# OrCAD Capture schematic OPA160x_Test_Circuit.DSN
size A; title: OPA160x, SoundPlus™ High-Performance, Bipolar-Input; rev: 1.4; note: Datasheet: SBOS474B   EVM: N/A
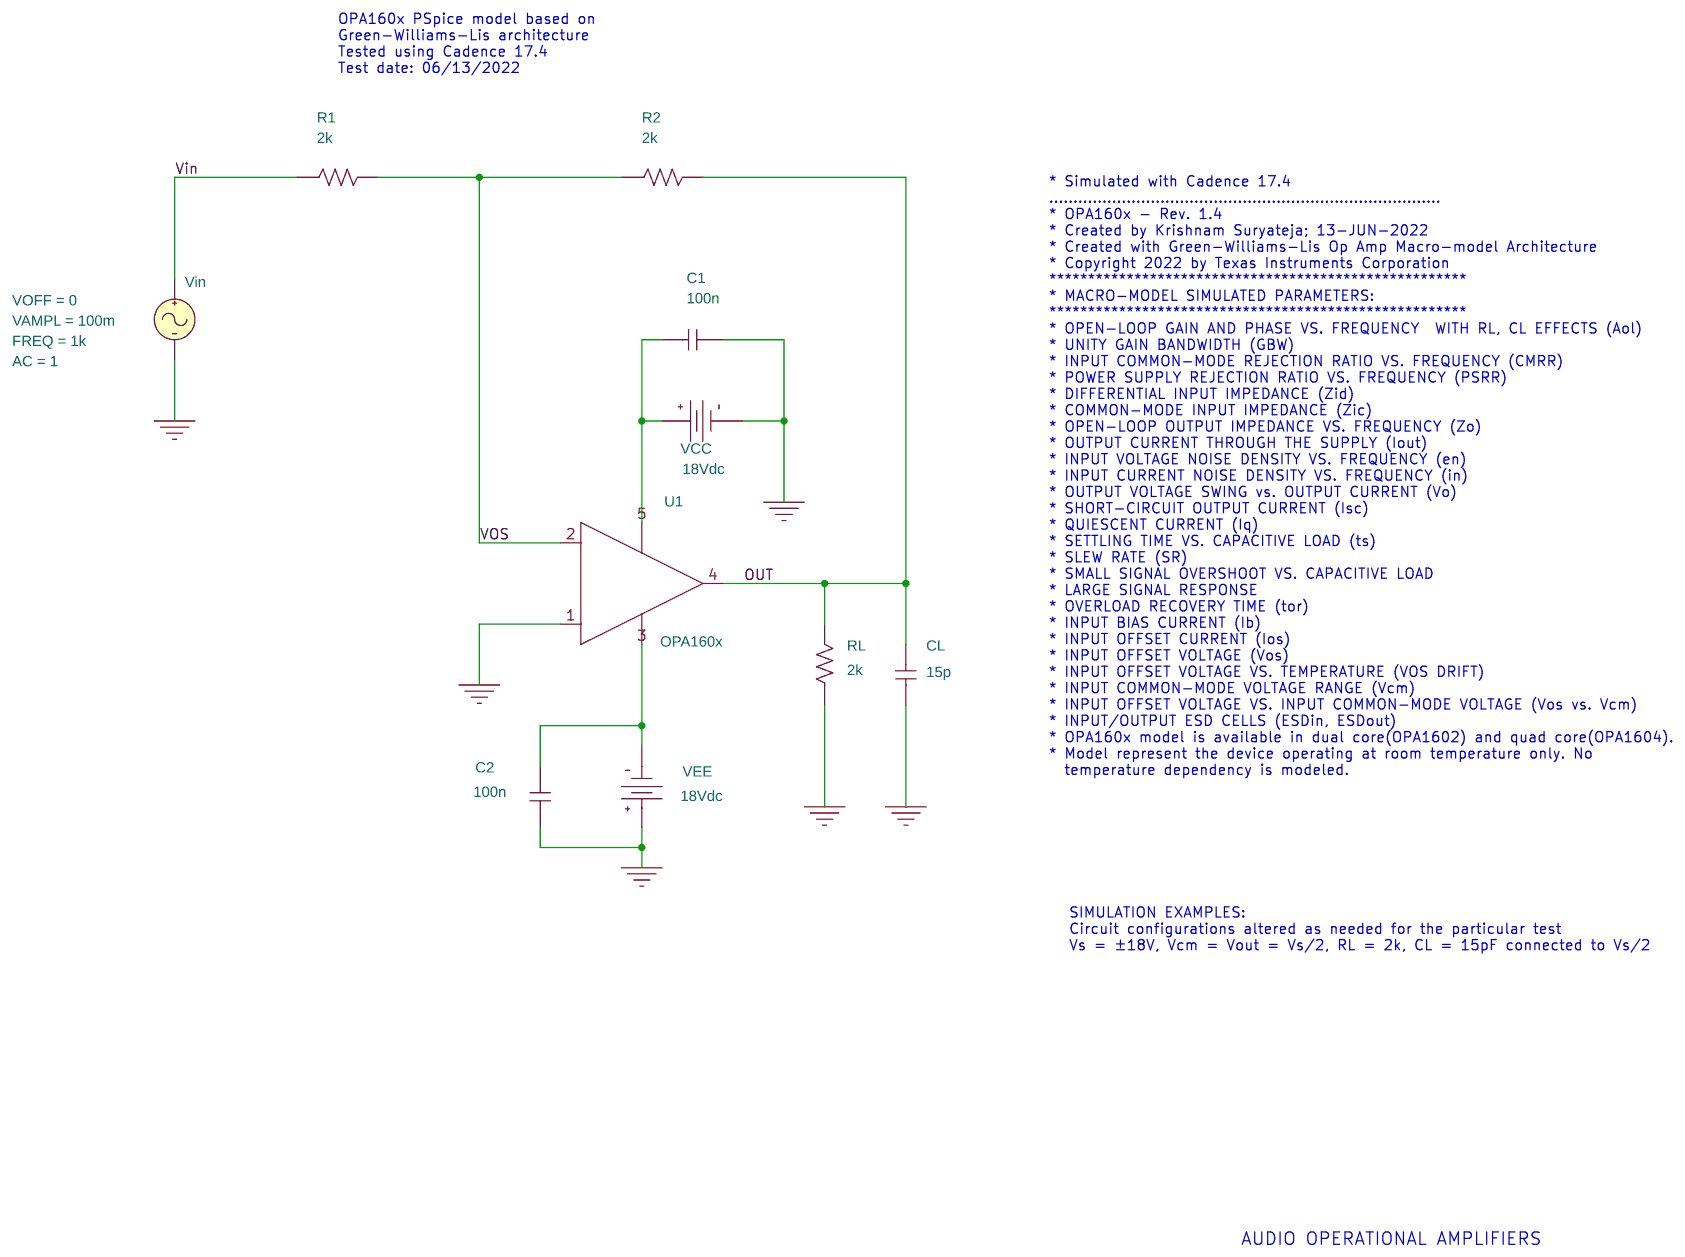
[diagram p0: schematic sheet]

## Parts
C1  100n  [cap196]
C2  100n  [cap196]
CL  15p  [cap196]
R1  2k  [AXRC05]
R2  2k  [AXRC05]
RL  2k  [AXRC05]
U1  OPA160x
VCC  VDC
VEE  VDC
Vin  VSIN

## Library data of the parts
C1 C2 CL = C
R1 R2 RL = R
U1 = OPA160x
VCC VEE = VDC: DC: 18Vdc
Vin = VSIN: AC: 1; FREQ: 1k; VAMPL: 100m; VOFF: 0

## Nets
Vin: R1.1 Vin.1(+)
0: C1.2 C2.1 CL.2 RL.1 U1.1(+) VCC.1(-) VEE.0(+) Vin.2(-)
OUT: CL.1 R2.2 RL.2 U1.4(OUT)
VOS: R1.2 R2.1 U1.2(-)
N27303: C1.1 U1.5(V+) VCC.0(+)
N27354: C2.2 U1.3(V-) VEE.1(-)

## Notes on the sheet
- OPA160x PSpice model based on
  Green-Williams-Lis architecture
  Tested using Cadence 17.4
  Test date: 06/13/2022
- * Simulated with Cadence 17.4
  .................................................................................
  * OPA160x - Rev. 1.4
  * Created by Krishnam Suryateja; 13-JUN-2022
  * Created with Green-Williams-Lis Op Amp Macro-model Architecture
  * Copyright 2022 by Texas Instruments Corporation
  ******************************************************
  * MACRO-MODEL SIMULATED PARAMETERS:
  ******************************************************
  * OPEN-LOOP GAIN AND PHASE VS. FREQUENCY  WITH RL, CL EFFECTS (Aol)
  * UNITY GAIN BANDWIDTH (GBW)
  * INPUT COMMON-MODE REJECTION RATIO VS. FREQUENCY (CMRR)
  * POWER SUPPLY REJECTION RATIO VS. FREQUENCY (PSRR)
  * DIFFERENTIAL INPUT IMPEDANCE (Zid)
  * COMMON-MODE INPUT IMPEDANCE (Zic)
  * OPEN-LOOP OUTPUT IMPEDANCE VS. FREQUENCY (Zo)
  * OUTPUT CURRENT THROUGH THE SUPPLY (Iout)
  * INPUT VOLTAGE NOISE DENSITY VS. FREQUENCY (en)
  * INPUT CURRENT NOISE DENSITY VS. FREQUENCY (in)
  * OUTPUT VOLTAGE SWING vs. OUTPUT CURRENT (Vo)
  * SHORT-CIRCUIT OUTPUT CURRENT (Isc)
  * QUIESCENT CURRENT (Iq)
  * SETTLING TIME VS. CAPACITIVE LOAD (ts)
  * SLEW RATE (SR)
  * SMALL SIGNAL OVERSHOOT VS. CAPACITIVE LOAD
  * LARGE SIGNAL RESPONSE
  * OVERLOAD RECOVERY TIME (tor)
  * INPUT BIAS CURRENT (Ib)
  * INPUT OFFSET CURRENT (Ios)
  * INPUT OFFSET VOLTAGE (Vos)
  * INPUT OFFSET VOLTAGE VS. TEMPERATURE (VOS DRIFT)
  * INPUT COMMON-MODE VOLTAGE RANGE (Vcm)
  * INPUT OFFSET VOLTAGE VS. INPUT COMMON-MODE VOLTAGE (Vos vs. Vcm)
  * INPUT/OUTPUT ESD CELLS (ESDin, ESDout)
  * OPA160x model is available in dual core(OPA1602) and quad core(OPA1604).
  * Model represent the device operating at room temperature only. No
    temperature dependency is modeled.
- SIMULATION EXAMPLES:
  Circuit configurations altered as needed for the particular test
  Vs = ±18V, Vcm = Vout = Vs/2, RL = 2k, CL = 15pF connected to Vs/2
- AUDIO OPERATIONAL AMPLIFIERS
